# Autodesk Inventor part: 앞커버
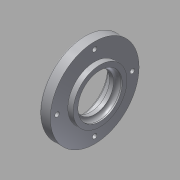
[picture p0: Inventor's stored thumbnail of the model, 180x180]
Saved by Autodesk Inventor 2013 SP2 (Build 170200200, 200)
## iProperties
Created: 2015-09
Part Number: 앞커버
Material: 알루미늄 6061
Document SubType Name: Modeling
Designer: mduedu
Density: 2.71 g/cm^3
Mass: 58.9874 g
Surface Area: 98.7754 cm^2
Volume: 21.7666 cm^3
Author: mduedu
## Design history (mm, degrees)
sketch "스케치1"
  geometry: L1 (-8, 67)-(-12, 67); L2 (-12, 67)-(-12, 80); L3 (-12, 80)-(-20, 80); L4 (-20, 80)-(-20, 70.5); L5 (-23, 70.5)-(-23, 61); L6 (-23, 61)-(-8, 61); L7 (-8, 61)-(-8, 67); L8 (-79.5, 39.5)-(-79.5, 54.5) reference; L9 (48.5, 54.5)-(48.5, 39.5) reference; L10 (-79.5, 47)-(48.5, 47); L11 (-20, 70.5)-(-23, 70.5); 3 further points
  constraints: 18 end point, 6 parallel, 4 midpoint, 1 horizontal, 1 perpendicular, 1 vertical alignment
  dimensions: "d0" = 15 distance between parallel lines of L7 L5; "d2" = 28 diameter of L6 L10; "d3" = 40 diameter of L1 L10; "d5" = 4 distance of L1.start L1.end; "d6" = 66 diameter of L3 L10; "d7" = 8 distance of L2.end L3.end; "d8" = 47 diameter of L4.end L10
revolve "회전1" sketch "스케치1" stored, may be unused: angle "d4" = 90 deg
sketch "스케치2"
  geometry: C1 r 33 at (0, 0) reference; 2 further points
  constraints: 1 coincident
hole "구멍1" sketch "스케치2" at (0, 0) diameter "d11" = 33; stored, may be unused: countersink angle "d15" = 90 deg, drill point angle "d17" = 0 deg; dims "d12" = 6, "d13" = 4, "d14" = 2, "d16" = 4
fillet "모깎기1" dims "d18" = 3
fillet "모깎기2" dims "d19" = 1
sketch "스케치3"
  geometry: C1 r 33 at (0, 0) reference; 2 further points
  constraints: 1 coincident
hole "구멍2" sketch "스케치3" at (0, 0) diameter "d20" = 40; stored, may be unused: countersink angle "d24" = 90 deg, drill point angle "d26" = 0 deg; dims "d21" = 6, "d22" = 4, "d23" = 2, "d25" = 8
fillet "모깎기3" dims "d27" = 0.4
chamfer "모따기1" distance "d28" = 1; stored, may be unused: second distance "d29" = 2, angle "d30" = 30 deg
sketch "스케치4" dims "d31" = 56
  geometry: C1 r 33 at (0, 0) reference; 6 further points
  constraints: 2 vertical alignment, 1 coincident, 7 other
  dimensions: "d36" = 360 deg dimension on C1.centre point (0, 28) (derived)
sketch "스케치7"
  geometry: 4 further points
hole "구멍4" sketch "스케치7" at (0, 28), (-28, 0), (28, 0), (0, -28) diameter "d48" = 3.4; stored, may be unused: countersink angle "d52" = 90 deg, drill point angle "d54" = 0 deg; dims "d49" = 6, "d50" = 6.5, "d51" = 3.4, "d53" = 8
node "솔리드1"
node "참조1"
node "참조2"
